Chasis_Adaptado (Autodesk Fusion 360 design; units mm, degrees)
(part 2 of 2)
sketch "Boceto53" plane through (0, 0, 6) normal (0, 0, 1) x axis (-1, 0, 0)
  line L1 (33.5, -113) -> (33.5, -130)
  line L2 (21.4163, -113) -> (33.5, -113)
  line L3 (-21.2752, -113) -> (21.4163, -113)
  line L4 (-33.5, -113) -> (-21.2752, -113)
  line L5 (-33.5, -130) -> (-33.5, -113)
  line L6 (33.5, -130) -> (-33.5, -130)
  line L7 (15, -118.5016) -> (21.4139, -118.5016)
  line L8 (15, -113) -> (15, -118.5016)
  line L9 (21.4139, -113) -> (15, -113)
  line L10 (21.4139, -118.5016) -> (21.4139, -113)
  line L11 (-15, -113) -> (15, -113)
  line L12 (-15, -115.5) -> (-15, -113)
  line L13 (15, -115.5) -> (-15, -115.5)
  line L14 (15, -113) -> (15, -115.5)
  line L15 (-21.2752, -118.5) -> (-15, -118.5)
  line L16 (-21.2752, -113) -> (-21.2752, -118.5)
  line L17 (-15, -113) -> (-21.2752, -113)
  line L18 (-15, -118.5) -> (-15, -113)
  point P10 (15, -113)
  point P5 (-21.2752, -113)
  point P17 (-21.2752, -113)
  horizontal L7
  vertical L8
  horizontal L9
  vertical L10
  coincident L3 P10
  horizontal L11
  vertical L12
  horizontal L13
  vertical L14
  horizontal L15
  vertical L16
  horizontal L17
  vertical L18
  coincident P5 P17
extrude "Extruir163" cut sketch "Boceto53" profile of L3 L7 L8 L9 L10 L11 L12 L13 L14 L15 L16 L17 L18 against normal blind 7
extrude "Extruir164" cut of existing geometry blind -1
extrude "Extruir165" cut of existing geometry blind -0.5
move "Move118"
move "Move119"
work_plane "WorkPlane2" AlongDistance 3.85 ExtraOffset 0
sketch "Sketch_Ajuste_Sensores_8ch" plane through (0, 0, 3.85) normal (0, 0, 1) x axis (1, 0, 0)
  line L1 (14.5, 56.5) -> (-14.5, 56.5)
  line L2 (14.5, 62.5) -> (14.5, 56.5)
  line L3 (-14.5, 62.5) -> (14.5, 62.5)
  line L4 (-14.5, 56.5) -> (-14.5, 62.5)
  circle C1 centre (-17.9, 61.55) radius 1.7
  circle C2 centre (17.9, 61.55) radius 1.7
extrude "Extrude166" cut sketch "Sketch_Ajuste_Sensores_8ch" along normal blind 3.5
work_plane "WorkPlane3" AlongDistance 41.44 ExtraOffset 0
sketch "Sketch_Bandeja_Base" plane through (0, 0, 41.44) normal (0, 0, 1) x axis (1, 0, 0)
  line L1 (29.8, -23) -> (-29.8, -23)
  line L2 (29.8, 72.5) -> (29.8, -23)
  line L3 (-29.8, 72.5) -> (29.8, 72.5)
  line L4 (-29.8, -23) -> (-29.8, 72.5)
work_plane "WorkPlane4" AlongDistance 44.44 ExtraOffset 0
sketch "Sketch_Cuna_54_9x90_8" plane through (0, 0, 44.44) normal (0, 0, 1) x axis (1, 0, 0)
  line L1 (27.8, -21) -> (-27.8, -21)
  line L2 (27.8, 70.5) -> (27.8, -21)
  line L3 (-27.8, 70.5) -> (27.8, 70.5)
  line L4 (-27.8, -21) -> (-27.8, 70.5)
  line L5 (16, 70) -> (-16, 70)
  line L6 (16, 73) -> (16, 70)
  line L7 (-16, 73) -> (16, 73)
  line L8 (-16, 70) -> (-16, 73)
  line L9 (6, -23.5) -> (-18, -23.5)
  line L10 (6, -20.5) -> (6, -23.5)
  line L11 (-18, -20.5) -> (6, -20.5)
  line L12 (-18, -23.5) -> (-18, -20.5)
  line L13 (-27.3, 8) -> (-30.2, 8)
  line L14 (-27.3, 28) -> (-27.3, 8)
  line L15 (-30.2, 28) -> (-27.3, 28)
  line L16 (-30.2, 8) -> (-30.2, 28)
  line L17 (30.2, 8) -> (27.3, 8)
  line L18 (30.2, 28) -> (30.2, 8)
  line L19 (27.3, 28) -> (30.2, 28)
  line L20 (27.3, 8) -> (27.3, 28)
sketch "Sketch_Ventanas_Y_Tornillos_M3" plane through (0, 0, 44.44) normal (0, 0, 1) x axis (1, 0, 0)
  line L1 (20, -12) -> (-20, -12)
  line L2 (20, 21) -> (20, -12)
  line L3 (-20, 21) -> (20, 21)
  line L4 (-20, -12) -> (-20, 21)
  line L5 (20, 28) -> (-20, 28)
  line L6 (20, 61) -> (20, 28)
  line L7 (-20, 61) -> (20, 61)
  line L8 (-20, 28) -> (-20, 61)
  line L9 (-20, 9.5) -> (-25.5, 9.5)
  line L10 (-20, 15.5) -> (-20, 9.5)
  line L11 (-25.5, 15.5) -> (-20, 15.5)
  line L12 (-25.5, 9.5) -> (-25.5, 15.5)
  line L13 (25.5, 9.5) -> (20, 9.5)
  line L14 (25.5, 15.5) -> (25.5, 9.5)
  line L15 (20, 15.5) -> (25.5, 15.5)
  line L16 (20, 9.5) -> (20, 15.5)
  line L17 (-9, -18) -> (-16, -18)
  line L18 (-9, -12) -> (-9, -18)
  line L19 (-16, -12) -> (-9, -12)
  line L20 (-16, -18) -> (-16, -12)
  circle C1 centre (-24.06, 65.01) radius 1.7
  circle C2 centre (24.04, -15.44) radius 1.7
sketch "Sketch_Avellanado_M3" plane through (0, 0, 44.44) normal (0, 0, 1) x axis (1, 0, 0)
  circle C1 centre (-24.06, 65.01) radius 3.1
  circle C2 centre (24.04, -15.44) radius 3.1
sketch "Sketch_Labio_Centrador_Body52" plane through (0, 0, 41.44) normal (0, 0, 1) x axis (1, 0, 0)
  line L1 (21.25, 29) -> (-21.15, 29)
  line L2 (21.25, 63.5) -> (21.25, 29)
  line L3 (-21.15, 63.5) -> (21.25, 63.5)
  line L4 (-21.15, 29) -> (-21.15, 63.5)
  line L5 (19.45, 29) -> (-19.35, 29)
  line L6 (19.45, 61.7) -> (19.45, 29)
  line L7 (-19.35, 61.7) -> (19.45, 61.7)
  line L8 (-19.35, 29) -> (-19.35, 61.7)
  line L9 (21.25, -13.5) -> (-8.5, -13.5)
  line L10 (21.25, 8.5) -> (21.25, -13.5)
  line L11 (-8.5, 8.5) -> (21.25, 8.5)
  line L12 (-8.5, -13.5) -> (-8.5, 8.5)
  line L13 (19.45, -11.7) -> (-8.5, -11.7)
  line L14 (19.45, 8.5) -> (19.45, -11.7)
  line L15 (-8.5, 8.5) -> (19.45, 8.5)
  line L16 (-8.5, -11.7) -> (-8.5, 8.5)
extrude "Extrude171" add sketch "Sketch_Labio_Centrador_Body52" profile of L1 L2 L3 L4 L6 L7 L8 L9 L10 L11 L12 L13 L14 against normal blind 1.5
work_plane "WorkPlane5" AlongDistance 53.94 ExtraOffset 0
sketch "Sketch_Marco_Pantalla_40x56_7" plane through (0, 0, 53.94) normal (0, 0, 1) x axis (1, 0, 0)
  line L1 (22.3, 7.7) -> (-22.3, 7.7)
  line L2 (22.3, 69) -> (22.3, 7.7)
  line L3 (-22.3, 69) -> (22.3, 69)
  line L4 (-22.3, 7.7) -> (-22.3, 69)
  line L5 (18.5, 11.5) -> (-18.5, 11.5)
  line L6 (18.5, 65.2) -> (18.5, 11.5)
  line L7 (-18.5, 65.2) -> (18.5, 65.2)
  line L8 (-18.5, 11.5) -> (-18.5, 65.2)
  line L9 (-22.3, 32) -> (-29.8, 32)
  line L10 (-22.3, 44) -> (-22.3, 32)
  line L11 (-29.8, 44) -> (-22.3, 44)
  line L12 (-29.8, 32) -> (-29.8, 44)
  line L13 (29.8, 32) -> (22.3, 32)
  line L14 (29.8, 44) -> (29.8, 32)
  line L15 (22.3, 44) -> (29.8, 44)
  line L16 (22.3, 32) -> (22.3, 44)
work_plane "WorkPlane6" AlongDistance 55.44 ExtraOffset 0
sketch "Sketch_Cuna_40x56_7" plane through (0, 0, 55.44) normal (0, 0, 1) x axis (1, 0, 0)
  line L1 (20.3, 9.7) -> (-20.3, 9.7)
  line L2 (20.3, 67) -> (20.3, 9.7)
  line L3 (-20.3, 67) -> (20.3, 67)
  line L4 (-20.3, 9.7) -> (-20.3, 67)
sketch "Sketch_Pilares_Shield" plane through (0, 0, 53.94) normal (0, 0, 1) x axis (1, 0, 0)
  line L1 (-27.8, 32) -> (-29.8, 32)
  line L2 (-27.8, 44) -> (-27.8, 32)
  line L3 (-29.8, 44) -> (-27.8, 44)
  line L4 (-29.8, 32) -> (-29.8, 44)
  line L5 (29.8, 32) -> (27.8, 32)
  line L6 (29.8, 44) -> (29.8, 32)
  line L7 (27.8, 44) -> (29.8, 44)
  line L8 (27.8, 32) -> (27.8, 44)
extrude "Extrude174" add sketch "Sketch_Pilares_Shield" against normal blind 5
work_plane "WorkPlane7" AlongDistance 41.44 ExtraOffset 0
sketch "Sketch_Bandeja_Exterior_113_8x63_8" plane through (0, 0, 41.44) normal (0, 0, 1) x axis (1, 0, 0)
  line L1 (31.9, -30) -> (-31.9, -30)
  line L2 (31.9, 83.8) -> (31.9, -30)
  line L3 (-31.9, 83.8) -> (31.9, 83.8)
  line L4 (-31.9, -30) -> (-31.9, 83.8)
work_plane "WorkPlane8" AlongDistance 44.44 ExtraOffset 0
sketch "Sketch_Cuna_59_8x109_8" plane through (0, 0, 44.44) normal (0, 0, 1) x axis (1, 0, 0)
  line L1 (29.9, -28) -> (-29.9, -28)
  line L2 (29.9, 81.8) -> (29.9, -28)
  line L3 (-29.9, 81.8) -> (29.9, 81.8)
  line L4 (-29.9, -28) -> (-29.9, 81.8)
  line L5 (17, 81) -> (-17, 81)
  line L6 (17, 84.5) -> (17, 81)
  line L7 (-17, 84.5) -> (17, 84.5)
  line L8 (-17, 81) -> (-17, 84.5)
  line L9 (8, -30.5) -> (-19, -30.5)
  line L10 (8, -27.5) -> (8, -30.5)
  line L11 (-19, -27.5) -> (8, -27.5)
  line L12 (-19, -30.5) -> (-19, -27.5)
  line L13 (-29.5, 6) -> (-32.5, 6)
  line L14 (-29.5, 26) -> (-29.5, 6)
  line L15 (-32.5, 26) -> (-29.5, 26)
  line L16 (-32.5, 6) -> (-32.5, 26)
  line L17 (32.5, 6) -> (29.5, 6)
  line L18 (32.5, 26) -> (32.5, 6)
  line L19 (29.5, 26) -> (32.5, 26)
  line L20 (29.5, 6) -> (29.5, 26)
sketch "Sketch_Ventanas_Piso_109x59" plane through (0, 0, 44.44) normal (0, 0, 1) x axis (1, 0, 0)
  line L1 (19.5, -24) -> (-20, -24)
  line L2 (19.5, 18) -> (19.5, -24)
  line L3 (-20, 18) -> (19.5, 18)
  line L4 (-20, -24) -> (-20, 18)
  line L5 (20, 24) -> (-20, 24)
  line L6 (20, 52) -> (20, 24)
  line L7 (-20, 52) -> (20, 52)
  line L8 (-20, 24) -> (-20, 52)
  line L9 (20, 56) -> (-19.5, 56)
  line L10 (20, 78) -> (20, 56)
  line L11 (-19.5, 78) -> (20, 78)
  line L12 (-19.5, 56) -> (-19.5, 78)
  line L13 (-20, 9.5) -> (-27.5, 9.5)
  line L14 (-20, 15.5) -> (-20, 9.5)
  line L15 (-27.5, 15.5) -> (-20, 15.5)
  line L16 (-27.5, 9.5) -> (-27.5, 15.5)
  line L17 (27.5, 9.5) -> (19.5, 9.5)
  line L18 (27.5, 15.5) -> (27.5, 9.5)
  line L19 (19.5, 15.5) -> (27.5, 15.5)
  line L20 (19.5, 9.5) -> (19.5, 15.5)
  circle C1 centre (-24.06, 65.01) radius 1.7
  circle C2 centre (24.04, -15.44) radius 1.7
sketch "Sketch_Avellanado_M3_109x59" plane through (0, 0, 44.44) normal (0, 0, 1) x axis (1, 0, 0)
  circle C1 centre (-24.06, 65.01) radius 3.1
  circle C2 centre (24.04, -15.44) radius 3.1
sketch "Sketch_Labio_Centrador_109x59" plane through (0, 0, 41.44) normal (0, 0, 1) x axis (1, 0, 0)
  line L1 (-19.35, 24) -> (-21.15, 24)
  line L2 (-19.35, 52) -> (-19.35, 24)
  line L3 (-21.15, 52) -> (-19.35, 52)
  line L4 (-21.15, 24) -> (-21.15, 52)
  line L5 (21.25, 24) -> (19.45, 24)
  line L6 (21.25, 52) -> (21.25, 24)
  line L7 (19.45, 52) -> (21.25, 52)
  line L8 (19.45, 24) -> (19.45, 52)
  line L9 (19.45, -13.5) -> (-8.5, -13.5)
  line L10 (19.45, -11.7) -> (19.45, -13.5)
  line L11 (-8.5, -11.7) -> (19.45, -11.7)
  line L12 (-8.5, -13.5) -> (-8.5, -11.7)
extrude "Extrude179" add sketch "Sketch_Labio_Centrador_109x59" against normal blind 1.5
work_plane "WorkPlane9" AlongDistance 59.94 ExtraOffset 0
sketch "Sketch_Marco_Pantalla_62_2x36_7" plane through (0, 0, 59.94) normal (0, 0, 1) x axis (1, 0, 0)
  line L1 (20.7, 3) -> (-20.7, 3)
  line L2 (20.7, 69.9) -> (20.7, 3)
  line L3 (-20.7, 69.9) -> (20.7, 69.9)
  line L4 (-20.7, 3) -> (-20.7, 69.9)
  line L5 (17, 6.7) -> (-17, 6.7)
  line L6 (17, 66.2) -> (17, 6.7)
  line L7 (-17, 66.2) -> (17, 66.2)
  line L8 (-17, 6.7) -> (-17, 66.2)
  line L9 (-20.7, 28) -> (-31.9, 28)
  line L10 (-20.7, 44) -> (-20.7, 28)
  line L11 (-31.9, 44) -> (-20.7, 44)
  line L12 (-31.9, 28) -> (-31.9, 44)
  line L13 (31.9, 28) -> (20.7, 28)
  line L14 (31.9, 44) -> (31.9, 28)
  line L15 (20.7, 44) -> (31.9, 44)
  line L16 (20.7, 28) -> (20.7, 44)
work_plane "WorkPlane10" AlongDistance 61.44 ExtraOffset 0
sketch "Sketch_Cuna_36_7x62_2" plane through (0, 0, 61.44) normal (0, 0, 1) x axis (1, 0, 0)
  line L1 (18.7, 5) -> (-18.7, 5)
  line L2 (18.7, 67.9) -> (18.7, 5)
  line L3 (-18.7, 67.9) -> (18.7, 67.9)
  line L4 (-18.7, 5) -> (-18.7, 67.9)
sketch "Sketch_Pilares_Shield_19_4" plane through (0, 0, 59.94) normal (0, 0, 1) x axis (1, 0, 0)
  line L1 (-29.9, 28) -> (-31.9, 28)
  line L2 (-29.9, 44) -> (-29.9, 28)
  line L3 (-31.9, 44) -> (-29.9, 44)
  line L4 (-31.9, 28) -> (-31.9, 44)
  line L5 (31.9, 28) -> (29.9, 28)
  line L6 (31.9, 44) -> (31.9, 28)
  line L7 (29.9, 44) -> (31.9, 44)
  line L8 (29.9, 28) -> (29.9, 44)
extrude "Extrude182" add sketch "Sketch_Pilares_Shield_19_4" against normal blind 9.5
work_plane "WorkPlane11" AlongDistance 41.44 ExtraOffset 0
sketch "Sketch_Bandeja_Final_Base" plane through (0, 0, 41.44) normal (0, 0, 1) x axis (1, 0, 0)
  line L1 (31.9, -30) -> (-31.9, -30)
  line L2 (31.9, 83.8) -> (31.9, -30)
  line L3 (-31.9, 83.8) -> (31.9, 83.8)
  line L4 (-31.9, -30) -> (-31.9, 83.8)
extrude "Extrude183" new body sketch "Sketch_Bandeja_Final_Base" along normal blind 9 bodies "Bandeja_Placa_Madre"
work_plane "WorkPlane12" AlongDistance 44.44 ExtraOffset 0
sketch "Sketch_Cuna_Final_59_8x109_8" plane through (0, 0, 44.44) normal (0, 0, 1) x axis (1, 0, 0)
  line L1 (29.9, -28) -> (-29.9, -28)
  line L2 (29.9, 81.8) -> (29.9, -28)
  line L3 (-29.9, 81.8) -> (29.9, 81.8)
  line L4 (-29.9, -28) -> (-29.9, 81.8)
  line L5 (22, 81) -> (-22, 81)
  line L6 (22, 84.5) -> (22, 81)
  line L7 (-22, 84.5) -> (22, 84.5)
  line L8 (-22, 81) -> (-22, 84.5)
  line L9 (22, -30.5) -> (-22, -30.5)
  line L10 (22, -27.5) -> (22, -30.5)
  line L11 (-22, -27.5) -> (22, -27.5)
  line L12 (-22, -30.5) -> (-22, -27.5)
  line L13 (-29.5, 4) -> (-32.5, 4)
  line L14 (-29.5, 28) -> (-29.5, 4)
  line L15 (-32.5, 28) -> (-29.5, 28)
  line L16 (-32.5, 4) -> (-32.5, 28)
  line L17 (32.5, 4) -> (29.5, 4)
  line L18 (32.5, 28) -> (32.5, 4)
  line L19 (29.5, 28) -> (32.5, 28)
  line L20 (29.5, 4) -> (29.5, 28)
extrude "Extrude184" cut sketch "Sketch_Cuna_Final_59_8x109_8" along normal blind 6.5
sketch "Sketch_Ventanas_Amplias_Final" plane through (0, 0, 44.44) normal (0, 0, 1) x axis (1, 0, 0)
  line L1 (19.5, -25.6) -> (-27.5, -25.6)
  line L2 (19.5, 20) -> (19.5, -25.6)
  line L3 (-27.5, 20) -> (19.5, 20)
  line L4 (-27.5, -25.6) -> (-27.5, 20)
  line L5 (27.5, -10) -> (19.5, -10)
  line L6 (27.5, 20) -> (27.5, -10)
  line L7 (19.5, 20) -> (27.5, 20)
  line L8 (19.5, -10) -> (19.5, 20)
  line L9 (27.5, 25) -> (-27.5, 25)
  line L10 (27.5, 53) -> (27.5, 25)
  line L11 (-27.5, 53) -> (27.5, 53)
  line L12 (-27.5, 25) -> (-27.5, 53)
  line L13 (27.5, 58) -> (-19.5, 58)
  line L14 (27.5, 79.4) -> (27.5, 58)
  line L15 (-19.5, 79.4) -> (27.5, 79.4)
  line L16 (-19.5, 58) -> (-19.5, 79.4)
  circle C1 centre (-24.06, 65.01) radius 1.7
  circle C2 centre (24.04, -15.44) radius 1.7
extrude "Extrude185" cut sketch "Sketch_Ventanas_Amplias_Final" against normal blind 3.5
sketch "Sketch_Avellanado_Final" plane through (0, 0, 44.44) normal (0, 0, 1) x axis (1, 0, 0)
  circle C1 centre (-24.06, 65.01) radius 3.1
  circle C2 centre (24.04, -15.44) radius 3.1
extrude "Extrude186" cut sketch "Sketch_Avellanado_Final" against normal blind 1.8
sketch "Sketch_Labio_Centrador_Final" plane through (0, 0, 41.44) normal (0, 0, 1) x axis (1, 0, 0)
  line L1 (-18.5, 20) -> (-21.15, 20)
  line L2 (-18.5, 25) -> (-18.5, 20)
  line L3 (-21.15, 25) -> (-18.5, 25)
  line L4 (-21.15, 20) -> (-21.15, 25)
  line L5 (21.25, 20) -> (18.5, 20)
  line L6 (21.25, 25) -> (21.25, 20)
  line L7 (18.5, 25) -> (21.25, 25)
  line L8 (18.5, 20) -> (18.5, 25)
  line L9 (-18.5, 53) -> (-21.15, 53)
  line L10 (-18.5, 58) -> (-18.5, 53)
  line L11 (-21.15, 58) -> (-18.5, 58)
  line L12 (-21.15, 53) -> (-21.15, 58)
  line L13 (21.25, 53) -> (18.5, 53)
  line L14 (21.25, 58) -> (21.25, 53)
  line L15 (18.5, 58) -> (21.25, 58)
  line L16 (18.5, 53) -> (18.5, 58)
extrude "Extrude187" add sketch "Sketch_Labio_Centrador_Final" against normal blind 1.5
sketch "Sketch76" plane through (0, 0, 0) normal (1, 0, 0) x axis (0, 0, -1)
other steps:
derived_base_feature "Operación base derivada1"
derived_base_feature "Operación base derivada1"
derived_base_feature "Operación base derivada1"
derived_base_feature "Operación base derivada1"
derived_base_feature "Operación base derivada1"
derived_base_feature "Operación base derivada1"
derived_base_feature "Operación base derivada1"
derived_base_feature "Operación base derivada1"
derived_base_feature "Operación base derivada1"
base_feature "Elemento base1"
base_feature "Elemento base2"
base_feature "Elemento base3"
base_feature "Elemento base4"
base_feature "Elemento base6"
base_feature "Elemento base7"
base_feature "Elemento base8"
base_feature "Elemento base9"
base_feature "Elemento base16"
base_feature "Elemento base17"
base_feature "Elemento base18"
base_feature "Elemento base19"
base_feature "Elemento base20"
base_feature "Elemento base21"
create_component "CrearComponentes1"
create_component "CrearComponentes2"
create_component "CrearComponentes3"
create_component "CrearComponentes4"
create_component "CrearComponentes5"
create_component "CrearComponentes6"
create_component "CrearComponentes7"
create_component "CrearComponentes8"
create_component "CrearComponentes54"
named bodies: "Bandeja_Placa_Madre"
